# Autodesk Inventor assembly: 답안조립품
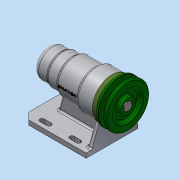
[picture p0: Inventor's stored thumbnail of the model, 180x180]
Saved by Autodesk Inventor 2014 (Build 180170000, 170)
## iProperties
Created: 2017-09
Part Number: 답안조립품
Document SubType Name: Weldment
Designer: kb542-16
Weld Material: Welded Aluminum-6061
Author: kb542-16
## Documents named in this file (12)
- C:\Users\kb542-16\Desktop\470907V1014\답안조립품.iam
- C:\Users\kb542-16\Desktop\470907V1014\본체.ipt
- C:\Users\kb542-16\Desktop\470907V1014\V벨트풀리.ipt
- C:\Users\kb542-16\Desktop\470907V1014\멈춤나사 M3x8.ipt
- C:\Users\kb542-16\Desktop\470907V1014\베어링 6004.ipt
- C:\Users\kb542-16\Desktop\470907V1014\베어링 51202.ipt
- C:\Users\kb542-16\Desktop\470907V1014\볼트 M4 x 12.ipt
- C:\Users\kb542-16\Desktop\470907V1014\어댑터슬리브.ipt
- C:\Users\kb542-16\Desktop\470907V1014\오일 실 20x35x7.ipt
- C:\Users\kb542-16\Desktop\470907V1014\축.ipt
- C:\Users\kb542-16\Desktop\470907V1014\커버.ipt
- C:\Users\kb542-16\Desktop\470907V1014\키 5 x 5 x 16.ipt
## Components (1 placed, 1 different names)
1. V벨트풀리:1 — 각도:2
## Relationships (1: Angle 1)
- 각도:2 [Angle]: V벨트풀리:1
